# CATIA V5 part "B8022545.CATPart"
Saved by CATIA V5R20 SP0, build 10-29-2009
Part number: B8022545
Revision: 9
Definition: design
Nomenclature: B8022545
Source: made
Description: NOT SPECIFIED
Bounding box of the stored display mesh (mm): x -22.5 to 22.5, y -22.5 to 22.5, z -10 to 45
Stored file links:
  C:\Users\Utente\Desktop\3D files B802\B8022545.CATPart
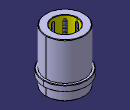
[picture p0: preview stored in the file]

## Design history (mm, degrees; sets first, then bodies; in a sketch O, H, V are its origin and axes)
Body1 "MANIFOLD_SOLID_BREP #38" (main body)
  Solid1: solid without history
Body2 "MANIFOLD_SOLID_BREP #76"
  Solid2: solid without history
Body3 "MANIFOLD_SOLID_BREP #114"
  Solid3: solid without history
Body4 "MANIFOLD_SOLID_BREP #152"
  Solid4: solid without history
Body5 "MANIFOLD_SOLID_BREP #190"
  Solid5: solid without history
Body6 "MANIFOLD_SOLID_BREP #228"
  Solid6: solid without history
Body7 "MANIFOLD_SOLID_BREP #266"
  Solid7: solid without history
Body8 "MANIFOLD_SOLID_BREP #304"
  Solid8: solid without history
Body9 "MANIFOLD_SOLID_BREP #2368"
  Solid9: solid without history
Body10 "MANIFOLD_SOLID_BREP #2406"
  Solid10: solid without history
Body11 "MANIFOLD_SOLID_BREP #2444"
  Solid11: solid without history
Body12 "MANIFOLD_SOLID_BREP #2482"
  Solid12: solid without history
Body13 "MANIFOLD_SOLID_BREP #2520"
  Solid13: solid without history
Body14 "MANIFOLD_SOLID_BREP #2558"
  Solid14: solid without history
Body15 "MANIFOLD_SOLID_BREP #2596"
  Solid15: solid without history
Body16 "MANIFOLD_SOLID_BREP #2634"
  Solid16: solid without history
Body17 "MANIFOLD_SOLID_BREP #2672"
  Solid17: solid without history
Body18 "MANIFOLD_SOLID_BREP #2710"
  Solid18: solid without history
Body19 "MANIFOLD_SOLID_BREP #2748"
  Solid19: solid without history
Body20 "MANIFOLD_SOLID_BREP #2786"
  Solid20: solid without history
Body21 "MANIFOLD_SOLID_BREP #2824"
  Solid21: solid without history
Body22 "MANIFOLD_SOLID_BREP #2862"
  Solid22: solid without history
Body23 "MANIFOLD_SOLID_BREP #2900"
  Solid23: solid without history
Body24 "MANIFOLD_SOLID_BREP #2938"
  Solid24: solid without history
Body25 "MANIFOLD_SOLID_BREP #2976"
  Solid25: solid without history
Body26 "MANIFOLD_SOLID_BREP #3014"
  Solid26: solid without history
Body27 "MANIFOLD_SOLID_BREP #3052"
  Solid27: solid without history
Body28 "MANIFOLD_SOLID_BREP #3090"
  Solid28: solid without history
Body29 "MANIFOLD_SOLID_BREP #3128"
  Solid29: solid without history
Body30 "MANIFOLD_SOLID_BREP #3166"
  Solid30: solid without history
Body31 "MANIFOLD_SOLID_BREP #3204"
  Solid31: solid without history
Body32 "MANIFOLD_SOLID_BREP #3242"
  Solid32: solid without history
Body33 "MANIFOLD_SOLID_BREP #3280"
  Solid33: solid without history
Body34 "MANIFOLD_SOLID_BREP #3318"
  Solid34: solid without history
Body35 "MANIFOLD_SOLID_BREP #3356"
  Solid35: solid without history
Body36 "MANIFOLD_SOLID_BREP #3394"
  Solid36: solid without history
Body37 "MANIFOLD_SOLID_BREP #3432"
  Solid37: solid without history
Body38 "MANIFOLD_SOLID_BREP #3470"
  Solid38: solid without history
Body39 "MANIFOLD_SOLID_BREP #3508"
  Solid39: solid without history
Body40 "MANIFOLD_SOLID_BREP #3546"
  Solid40: solid without history
Body41 "MANIFOLD_SOLID_BREP #3584"
  Solid41: solid without history
Body42 "MANIFOLD_SOLID_BREP #3622"
  Solid42: solid without history
Body43 "MANIFOLD_SOLID_BREP #3660"
  Solid43: solid without history
Body44 "MANIFOLD_SOLID_BREP #3698"
  Solid44: solid without history
Body45 "MANIFOLD_SOLID_BREP #3736"
  Solid45: solid without history
Body46 "MANIFOLD_SOLID_BREP #3774"
  Solid46: solid without history
Body47 "MANIFOLD_SOLID_BREP #3812"
  Solid47: solid without history
Body48 "MANIFOLD_SOLID_BREP #3850"
  Solid48: solid without history
Body49 "MANIFOLD_SOLID_BREP #3888"
  Solid49: solid without history
Body50 "MANIFOLD_SOLID_BREP #3926"
  Solid50: solid without history
Body51 "MANIFOLD_SOLID_BREP #3964"
  Solid51: solid without history
Body52 "MANIFOLD_SOLID_BREP #4002"
  Solid52: solid without history
Body53 "MANIFOLD_SOLID_BREP #4040"
  Solid53: solid without history
Body54 "MANIFOLD_SOLID_BREP #4078"
  Solid54: solid without history
Body55 "MANIFOLD_SOLID_BREP #4116"
  Solid55: solid without history
Body56 "MANIFOLD_SOLID_BREP #4154"
  Solid56: solid without history
Body57 "MANIFOLD_SOLID_BREP #4192"
  Solid57: solid without history
Body58 "MANIFOLD_SOLID_BREP #4230"
  Solid58: solid without history
Body59 "MANIFOLD_SOLID_BREP #4268"
  Solid59: solid without history
Body60 "MANIFOLD_SOLID_BREP #4306"
  Solid60: solid without history
Body61 "MANIFOLD_SOLID_BREP #4344"
  Solid61: solid without history
Body62 "MANIFOLD_SOLID_BREP #4382"
  Solid62: solid without history
Body63 "MANIFOLD_SOLID_BREP #4420"
  Solid63: solid without history
Body64 "MANIFOLD_SOLID_BREP #4458"
  Solid64: solid without history
Body65 "MANIFOLD_SOLID_BREP #4496"
  Solid65: solid without history
Body66 "MANIFOLD_SOLID_BREP #4534"
  Solid66: solid without history
Body67 "MANIFOLD_SOLID_BREP #4572"
  Solid67: solid without history
Body68 "MANIFOLD_SOLID_BREP #4610"
  Solid68: solid without history
Body69 "MANIFOLD_SOLID_BREP #4648"
  Solid69: solid without history
Body70 "MANIFOLD_SOLID_BREP #4686"
  Solid70: solid without history
Body71 "MANIFOLD_SOLID_BREP #4724"
  Solid71: solid without history
Body72 "MANIFOLD_SOLID_BREP #4762"
  Solid72: solid without history
Body73 "MANIFOLD_SOLID_BREP #4800"
  Solid73: solid without history
Body74 "MANIFOLD_SOLID_BREP #4838"
  Solid74: solid without history
Body75 "MANIFOLD_SOLID_BREP #4876"
  Solid75: solid without history
Body76 "MANIFOLD_SOLID_BREP #4914"
  Solid76: solid without history
Body77 "MANIFOLD_SOLID_BREP #4952"
  Solid77: solid without history
Body78 "MANIFOLD_SOLID_BREP #4990"
  Solid78: solid without history
Body79 "MANIFOLD_SOLID_BREP #5028"
  Solid79: solid without history
Body80 "MANIFOLD_SOLID_BREP #5066"
  Solid80: solid without history
Body81 "MANIFOLD_SOLID_BREP #5104"
  Solid81: solid without history
Body82 "MANIFOLD_SOLID_BREP #5142"
  Solid82: solid without history
Body83 "MANIFOLD_SOLID_BREP #5180"
  Solid83: solid without history
Body84 "MANIFOLD_SOLID_BREP #5218"
  Solid84: solid without history
Body85 "MANIFOLD_SOLID_BREP #5256"
  Solid85: solid without history
Body86 "MANIFOLD_SOLID_BREP #5294"
  Solid86: solid without history
Body87 "MANIFOLD_SOLID_BREP #5332"
  Solid87: solid without history
Body88 "MANIFOLD_SOLID_BREP #5370"
  Solid88: solid without history
Body89 "MANIFOLD_SOLID_BREP #5408"
  Solid89: solid without history
Body90 "MANIFOLD_SOLID_BREP #5446"
  Solid90: solid without history
Body91 "MANIFOLD_SOLID_BREP #5484"
  Solid91: solid without history
Body92 "MANIFOLD_SOLID_BREP #5522"
  Solid92: solid without history
Body93 "MANIFOLD_SOLID_BREP #5560"
  Solid93: solid without history
Body94 "MANIFOLD_SOLID_BREP #5598"
  Solid94: solid without history
Body95 "MANIFOLD_SOLID_BREP #5636"
  Solid95: solid without history
Body96 "MANIFOLD_SOLID_BREP #5674"
  Solid96: solid without history
Body97 "MANIFOLD_SOLID_BREP #5712"
  Solid97: solid without history
Body98 "MANIFOLD_SOLID_BREP #5750"
  Solid98: solid without history
Body99 "MANIFOLD_SOLID_BREP #5788"
  Solid99: solid without history
Body100 "MANIFOLD_SOLID_BREP #5826"
  Solid100: solid without history
Body101 "MANIFOLD_SOLID_BREP #5864"
  Solid101: solid without history
Body102 "MANIFOLD_SOLID_BREP #5902"
  Solid102: solid without history
Body103 "MANIFOLD_SOLID_BREP #5940"
  Solid103: solid without history
Body104 "MANIFOLD_SOLID_BREP #5978"
  Solid104: solid without history
Body105 "MANIFOLD_SOLID_BREP #6016"
  Solid105: solid without history
Body106 "MANIFOLD_SOLID_BREP #6054"
  Solid106: solid without history
Body107 "MANIFOLD_SOLID_BREP #6092"
  Solid107: solid without history
Body108 "MANIFOLD_SOLID_BREP #6130"
  Solid108: solid without history
Body109 "MANIFOLD_SOLID_BREP #6168"
  Solid109: solid without history
Body110 "MANIFOLD_SOLID_BREP #6206"
  Solid110: solid without history
Body111 "MANIFOLD_SOLID_BREP #6244"
  Solid111: solid without history
Body112 "MANIFOLD_SOLID_BREP #6282"
  Solid112: solid without history
Body113 "MANIFOLD_SOLID_BREP #6320"
  Solid113: solid without history
Body114 "MANIFOLD_SOLID_BREP #6358"
  Solid114: solid without history
Body115 "MANIFOLD_SOLID_BREP #6396"
  Solid115: solid without history
Body116 "MANIFOLD_SOLID_BREP #6434"
  Solid116: solid without history
Body117 "MANIFOLD_SOLID_BREP #6472"
  Solid117: solid without history
Body118 "MANIFOLD_SOLID_BREP #6510"
  Solid118: solid without history
Body119 "MANIFOLD_SOLID_BREP #6548"
  Solid119: solid without history
Body120 "MANIFOLD_SOLID_BREP #6586"
  Solid120: solid without history
Body121 "MANIFOLD_SOLID_BREP #6624"
  Solid121: solid without history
